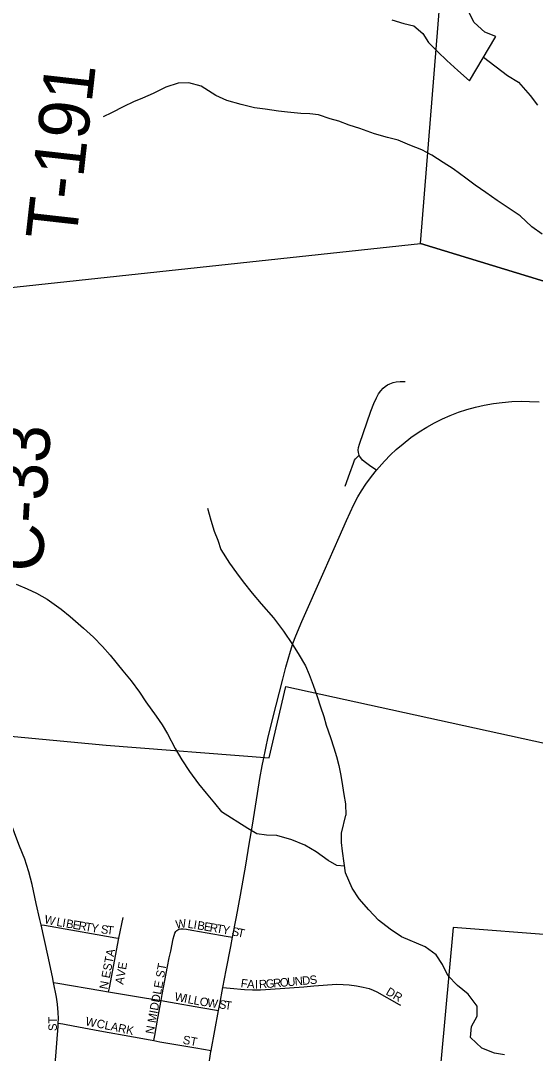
# Model space of a CAD drawing. Extents: x 1451455 to 1749751, y 218250 to 574981.
# Drawn here: x 1601082 to 1604125, y 319894 to 326004 of the extents above; entities that cross this region are included whole.
import ezdxf

# ---------------------------------------------------------------- set-up
doc = ezdxf.new("R2010")
doc.units = 0
for name, color, linetype in [('GM_X_City_Street', 7, 'Continuous'), ('GM_X_City_Street_Text', 7, 'Continuous'), ('GM_X_Corporation', 7, 'Continuous'), ('GM_X_County_Road_Text', 7, 'Continuous'), ('GM_X_Minor_Lake', 7, 'Continuous'), ('GM_X_Minor_River', 7, 'Continuous'), ('GM_X_Township', 7, 'Continuous'), ('GM_X_Township_Road', 7, 'Continuous'), ('GM_X_Township_Road_Text', 7, 'Continuous'), ('GM_X_US_Route', 7, 'Continuous')]:
    doc.layers.add(name, color=color, linetype=linetype)

msp = doc.modelspace()

# ---------------------------------------------------------------- linework, layer by layer
at = {"layer": 'GM_X_City_Street'}
for points in [[(1601202.2, 320655.4), (1601195.5, 320685.5), (1601173.4, 320781.2), (1601148.9, 320892.9), (1601129.4, 320968.8), (1601116, 321012.5), (1601105.3, 321043.3), (1601075.4, 321119.4), (1601052.1, 321177.2), (1601022.7, 321257.4), (1601007.2, 321304.1), (1600982.8, 321385.8), (1600965.6, 321452.7), (1600943.8, 321545.3), (1600893.7, 321743)], [(1601663, 320575.3), (1601686.8, 320698.7)], [(1601276.2, 320313.4), (1601269.8, 320346), (1601242.3, 320474.3), (1601202.2, 320655.4)], [(1601202.2, 320655.4), (1601223.1, 320651.7), (1601533.4, 320596.7), (1601643.6, 320578.5), (1601663, 320575.3)], [(1601912, 320206.7), (1601918.6, 320241.5), (1601950.3, 320408.7), (1601960.5, 320460), (1601969.3, 320497.9), (1601983.8, 320571.8), (1601988.7, 320590.7), (1601994.2, 320606), (1601998.9, 320614.6), (1602005.7, 320621.8)], [(1602005.7, 320621.8), (1602016.3, 320628.1), (1602027.9, 320631.1), (1602043.2, 320631.1), (1602061.5, 320628.9), (1602093.8, 320624), (1602184.2, 320607.5), (1602297.2, 320587.6), (1602334.5, 320581.1)], [(1601601.8, 320258.4), (1601606.2, 320281.2), (1601663, 320575.3)], [(1601304.3, 320073.5), (1601305.1, 320100.8), (1601303.8, 320136.6), (1601299.3, 320185.2), (1601293.2, 320227.2), (1601276.2, 320313.4)], [(1601276.2, 320313.4), (1601300.5, 320309.4), (1601556, 320266.1), (1601601.8, 320258.4)], [(1602277.8, 320283.6), (1602321.4, 320279.4), (1602406, 320271.3), (1602451.6, 320269.1), (1602500.6, 320270), (1602559.4, 320273), (1602755.6, 320288.3), (1602814.5, 320292.9), (1602952.2, 320302.6), (1602988.6, 320302.3), (1603024.9, 320299.6), (1603067.5, 320293.8), (1603106.4, 320286), (1603141.7, 320276.9), (1603166.9, 320268.2), (1603188.2, 320258.4), (1603319, 320183.2), (1603327.6, 320178.6)], [(1601601.8, 320258.4), (1601801.8, 320224.8), (1601912, 320206.7)], [(1601869.5, 319970.7), (1601874.6, 320000.1), (1601892.3, 320103.3), (1601912, 320206.7)], [(1601912, 320206.7), (1601966.8, 320197.8), (1602147.5, 320166.2), (1602252.4, 320147.8)], [(1601260.7, 319531.9), (1601262.4, 319553.9), (1601276.3, 319702.3), (1601303.8, 320055.2), (1601304.3, 320073.5)], [(1601304.3, 320073.5), (1601331, 320068.8), (1601350.4, 320065.4), (1601424.5, 320051.5), (1601550, 320027.4), (1601749.7, 319991.7), (1601848.3, 319975.1), (1601869.5, 319970.7)], [(1601869.5, 319970.7), (1601905.4, 319963.2), (1602117.7, 319926.2), (1602208.2, 319910.4)]]:
    msp.add_lwpolyline(points, dxfattribs=at)
at = {"layer": 'GM_X_Corporation'}
msp.add_lwpolyline([(1600894.4, 321782.8), (1601586.6, 321717.6), (1602551.4, 321643.6), (1602650.6, 322065), (1604467.4, 321666.3), (1604443, 321472.2), (1604960, 321426.4), (1604865.9, 320543.7), (1603638.6, 320637.9), (1603496, 319066.6), (1603830.6, 319069.7), (1603743.1, 318219.8), (1602805, 317104.4), (1602731.4, 316312), (1602198.9, 316262.9), (1602217.2, 315602.4), (1602057.6, 315622.4), (1601937.9, 314443.3)], dxfattribs=at)
at = {"layer": 'GM_X_Minor_Lake'}
for points in [[(1603891.1, 325911.1), (1603825.5, 325936.1), (1603764.3, 325993.1), (1603729.3, 326057.7)], [(1603277, 326010.1), (1603346.6, 325987.1), (1603406.4, 325974.2), (1603459.7, 325929.3), (1603492.9, 325874.8), (1603548.1, 325819.9), (1603601.3, 325769), (1603666.5, 325710), (1603735.5, 325648.9)], [(1603735.5, 325648.9), (1603891.1, 325911.1)]]:
    msp.add_lwpolyline(points, dxfattribs=at)
at = {"layer": 'GM_X_Minor_River'}
for points in [[(1603818.3, 325788.5), (1603959.8, 325679.7), (1604025.2, 325640.7), (1604094, 325561.6), (1604137.2, 325504.9)], [(1604166.4, 324741.1), (1604105.1, 324784), (1604036.1, 324849.1), (1603976.7, 324888.1), (1603899.4, 324939.3), (1603832.2, 324988.3), (1603768.9, 325031.3), (1603713.5, 325072.2), (1603638.3, 325127.3), (1603580.9, 325164.2), (1603513.6, 325209.3), (1603454.1, 325240.2), (1603382.5, 325267.3), (1603313, 325296.3), (1603251.3, 325313.2), (1603173.6, 325334.4), (1603088.1, 325365.7), (1603024.5, 325386.6), (1602962.9, 325409.5), (1602911.1, 325424.3), (1602843.5, 325447.3), (1602791.6, 325452.1), (1602737.7, 325454.8), (1602659.9, 325462), (1602606, 325468.8), (1602528.2, 325479.9), (1602464.4, 325488.8), (1602384.8, 325508), (1602301.2, 325531.2), (1602235.7, 325562.2), (1602148.5, 325617.6), (1602076.8, 325636.6), (1602012.9, 325633.6), (1601940.6, 325610.6), (1601866.1, 325573.6), (1601801.8, 325546.4), (1601749.5, 325523.1), (1601691.2, 325495.9), (1601618.8, 325458.9), (1601568.5, 325435.6)], [(1602185.5, 323120.5), (1602206.4, 323048.1), (1602225.5, 322983.7), (1602246.8, 322931.3), (1602266, 322875), (1602316.8, 322794.1), (1602358, 322737.4), (1602397.2, 322684.7), (1602450.2, 322617.8), (1602503.2, 322553), (1602576, 322471.8), (1602634.9, 322392.8), (1602689.7, 322313.9), (1602722.9, 322259.3), (1602765.9, 322186.5), (1602787.1, 322136.1), (1602812.2, 322071.7), (1602835.3, 322005.2), (1602854.4, 321944.8), (1602873.6, 321886.5), (1602888.9, 321836.1), (1602913.8, 321763.6), (1602932.9, 321701.3), (1602950.2, 321650.9), (1602963.4, 321596.6), (1602974.6, 321538.4), (1602985.7, 321476.1), (1602993, 321425.9), (1603002.2, 321369.7), (1603005.3, 321303.5)], [(1601054.2, 322670), (1601119.7, 322643), (1601175.3, 322616.1), (1601238.8, 322581.1), (1601321.9, 322521.8), (1601375.2, 322479), (1601452.2, 322409.8), (1601511.4, 322356.8), (1601564.6, 322302), (1601611.8, 322249.2), (1601686.4, 322158), (1601735.6, 322099.1), (1601784.6, 322030.3), (1601821.7, 321973.7), (1601882.5, 321888.7), (1601917.7, 321838.1), (1601949, 321785.5), (1601995.7, 321698.7), (1602034.7, 321630), (1602079.7, 321561.2), (1602132.6, 321488.3), (1602177.8, 321433.6), (1602227, 321374.8), (1602270.2, 321324.1)], [(1602997.3, 321001), (1602950.8, 321006.5), (1602899.1, 321035.3), (1602829.7, 321086.2), (1602762.1, 321125.2), (1602684.4, 321158.3), (1602596.7, 321183.5), (1602534.6, 321184.3), (1602478.7, 321193), (1602425, 321223.8), (1602270.2, 321324.1)], [(1603943.5, 319886), (1603883.6, 319894.8), (1603807.9, 319925.8), (1603742.6, 319988.8), (1603747.4, 320052.8), (1603780.2, 320114.4), (1603781, 320172.5), (1603727.8, 320245.3), (1603664.4, 320296.2), (1603607.1, 320355), (1603575.9, 320419.5), (1603538.6, 320476.1), (1603473.1, 320525), (1603333.8, 320582.9), (1603266.3, 320629.9), (1603196.9, 320682.9), (1603139.6, 320743.7), (1603082.4, 320808.5), (1603041.1, 320871.2), (1603002.2, 320961.8), (1602995, 321020), (1602983.8, 321090.2), (1602978.5, 321142.3), (1602979.2, 321196.4), (1603005.3, 321303.5)]]:
    msp.add_lwpolyline(points, dxfattribs=at)
at = {"layer": 'GM_X_Township'}
for points in [[(1615589.3, 321106.6), (1615010.3, 321279.4), (1612831.2, 321883.2), (1608561, 323144.8), (1605657, 324014), (1605007.7, 324208.4), (1603446, 324685.1), (1604039.4, 332057.3), (1604326.7, 335626.5), (1604589.6, 338933.2), (1605120, 345606.5), (1605455, 350781)], [(1576824.8, 327623), (1581500.7, 324963.5), (1586071.6, 322358.5), (1586366.1, 322190.7), (1590293, 322987.2), (1593030.5, 323584.8), (1593145.7, 323595.7), (1593983, 323674.9), (1599358.9, 324248.8), (1600819.8, 324404.7), (1603446, 324685.1), (1604039.4, 332057.3)], [(1593145.7, 323595.7), (1593983, 323674.9), (1599358.9, 324248.8), (1600819.8, 324404.7), (1603446, 324685.1), (1605007.7, 324208.4), (1605657, 324014), (1608561, 323144.8), (1612831.2, 321883.2), (1615010.3, 321279.4), (1615589.3, 321106.6)]]:
    msp.add_lwpolyline(points, dxfattribs=at)
at = {"layer": 'GM_X_Township_Road'}
for points in [[(1603082.8, 323433.8), (1603078.7, 323449.6), (1603078.2, 323462.7), (1603080.1, 323479), (1603085.3, 323498.1), (1603152.8, 323693.9), (1603170.4, 323739.8), (1603185.4, 323772.6), (1603198.3, 323795.5), (1603211.4, 323814.4), (1603224.4, 323829.2), (1603236.7, 323840), (1603250.3, 323849.1), (1603265, 323856.4), (1603283.7, 323862.7), (1603303, 323866.9), (1603325.9, 323869.5), (1603355.5, 323869.9)], [(1603000.8, 323250.2), (1603028.5, 323326.9), (1603049, 323385.4), (1603056.7, 323403.3), (1603062, 323411.4), (1603064.2, 323413.9), (1603082.8, 323433.8)], [(1603185.8, 323344.9), (1603152.6, 323366.4), (1603144.3, 323371.7), (1603120.4, 323389.2), (1603103, 323404.2), (1603092.2, 323416.7), (1603085.3, 323427.8), (1603082.8, 323433.8)]]:
    msp.add_lwpolyline(points, dxfattribs=at)
at = {"layer": 'GM_X_US_Route'}
for points in [[(1602631.8, 322108.1), (1602650.4, 322179.9), (1602677.5, 322274.7), (1602691.6, 322318.6), (1602708.9, 322364.8), (1602744.2, 322449.9), (1602875.8, 322746.8), (1602964.2, 322947.9), (1603007.5, 323047.3), (1603052.2, 323142.5), (1603075.2, 323186.2), (1603097, 323223.2), (1603122.4, 323261.8), (1603155.4, 323307), (1603185.8, 323344.9), (1603186.4, 323345.5), (1603232.2, 323397.3), (1603269, 323435.1), (1603302.7, 323466.6), (1603342.7, 323500.8), (1603389.5, 323537.2), (1603437.9, 323571.4), (1603482.5, 323599.6), (1603528.5, 323625.4), (1603575.8, 323648.6), (1603621.1, 323668.2), (1603670.3, 323687), (1603720.4, 323703.3), (1603771.2, 323717.4), (1603822.5, 323729.2), (1603877.6, 323738.9), (1603929.9, 323745.5), (1603985.7, 323750.1), (1604044.9, 323752.1), (1604090.9, 323751.5), (1604146.8, 323748.9)], [(1602509.2, 321594.9), (1602517.3, 321633.4), (1602545.7, 321766.3), (1602591.8, 321954.4), (1602631.8, 322108.1)], [(1602412.3, 321007.3), (1602433.3, 321131.6), (1602452.5, 321244.8), (1602481.9, 321432.5), (1602495.8, 321519.9), (1602509.2, 321594.9)], [(1602056.2, 318918.3), (1602057.4, 318932.3), (1602071.9, 319118.8), (1602081, 319200.4), (1602089.5, 319255.7), (1602103.8, 319329.9), (1602114.2, 319381.4), (1602120.8, 319415.1), (1602134.9, 319487.7), (1602158.6, 319610), (1602191.6, 319810.6), (1602207.1, 319904.6), (1602208.2, 319910.4), (1602252.4, 320147.8), (1602259.4, 320185.3), (1602277.8, 320283.6), (1602296.9, 320385.4), (1602324.4, 320527.1), (1602334.5, 320581.1), (1602357.1, 320701.3), (1602382.1, 320830.1), (1602412.3, 321007.3)]]:
    msp.add_lwpolyline(points, dxfattribs=at)

# ---------------------------------------------------------------- texts
at = {"layer": 'GM_X_City_Street_Text'}
for s, rotation, p in [('W', 345.88628, (1601217.5, 320665.7)), ('L', 350.4209, (1601290.7, 320648.8)), ('I', 350.4011, (1601325.4, 320642.9)), ('B', 350.42018, (1601347.1, 320639.2)), ('E', 350.4209, (1601386.1, 320632.6)), ('R', 350.4099, (1601420.8, 320626.8)), ('T', 350.42639, (1601459.9, 320620.2)), ('Y', 350.8259, (1601495, 320614.3)), ('W', 7.26684, (1602000.6, 320631.6)), ('L', 351.74623, (1602066.8, 320637.4)), ('I', 350.6455, (1602101.4, 320632.4)), ('B', 350.44986, (1602123.1, 320628.8)), ('E', 350.32205, (1602162.1, 320622.2)), ('R', 350.31772, (1602196.8, 320616.3)), ('S', 352.48923, (1601553.1, 320605.1)), ('T', 352.57752, (1601588, 320600.5)), ('T', 350.32771, (1602235.9, 320609.7)), ('Y', 349.6717, (1602270.4, 320603.8)), ('S', 348.34984, (1602326.3, 320593.3)), ('T', 348.30971, (1602360.8, 320586.2)), ('N ESTA', 79.16078, (1601595, 320269.9)), ('AVE', 79.87383, (1601688.4, 320298.6)), ('N MIDDLE ST', 79.57992, (1601867.7, 320005.6)), ('S', 6.67798, (1602793.4, 320302.6)), ('F', 351.97034, (1602380.5, 320286.2)), ('A', 356.01818, (1602419.2, 320280.8)), ('I', 0.42554, (1602467.3, 320277.7)), ('R', 3.34249, (1602492, 320277.9)), ('G', 4.75686, (1602532.9, 320280.3)), ('R', 4.89373, (1602576.9, 320284)), ('O', 4.90976, (1602616.4, 320287.4)), ('U', 4.90158, (1602660.2, 320291.1)), ('N', 4.90976, (1602704.1, 320294.9)), ('D', 4.90158, (1602747.9, 320298.7)), ('W', 349.02305, (1601988.8, 320207)), ('I', 349.02038, (1602045, 320196.1)), ('L', 349.01955, (1602066.6, 320191.9)), ('L', 349.20137, (1602101.3, 320185.1)), ('DR', 329.53699, (1603237, 320245.4)), ('O', 350.99481, (1602137.6, 320178.2)), ('W', 351.85115, (1602181.8, 320171.2)), ('S', 351.86545, (1602251.5, 320161.3)), ('T', 351.87183, (1602286.4, 320156.3)), ('ST', 90, (1601295.6, 320026.1)), ('W', 347.01275, (1601461.1, 320061.7)), ('CLARK', 347.98848, (1601527, 320048.5)), ('ST', 349.3787, (1602037.1, 319951.8))]:
    msp.add_text(s, height=50, rotation=rotation, dxfattribs=at).set_placement(p)
at = {"layer": 'GM_X_County_Road_Text'}
msp.add_text('C-33', height=300, rotation=86.65835, dxfattribs=at).set_placement((1601209.6, 322737.5))
at = {"layer": 'GM_X_Township_Road_Text'}
msp.add_text('T-191', height=300, rotation=83.56773, dxfattribs=at).set_placement((1601408.9, 324694.1))

doc.saveas('drawing.dxf')
